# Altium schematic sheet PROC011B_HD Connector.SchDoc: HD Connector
size 431 x 279 mm; Date: Not shown in title block; ApprovedBy: Not shown in title block; CheckedBy: Not shown in title block; Author: Not shown in title block; CompanyName: Not shown in title block; Engineer: Not shown in title block; Organization: Not shown in title block; Address1: Not shown in title block; Address2: Not shown in title block; Address3: Not shown in title block; Address4: Not shown in title block; DocumentNumber: 1; Revision: Use project parameter SCH_Rev; SheetNumber: 11; SheetTotal: 17; PageSetup: Record=PageOptions¦CenterHorizontal=True¦CenterVertical=True¦PrintScale=1.00¦XCorrection=1.00¦YCorrection=1.00¦PrintKind=0¦BorderSize=5000000¦LeftOffset=0¦BottomOffset=0¦Orientation=2¦PaperLength=1000¦PaperWidth=1000¦Scale=100¦PaperSource=15¦PrintQuality=600¦MediaType=1¦DitherType=10¦PrintScaleMode=1¦PaperKind=Letter
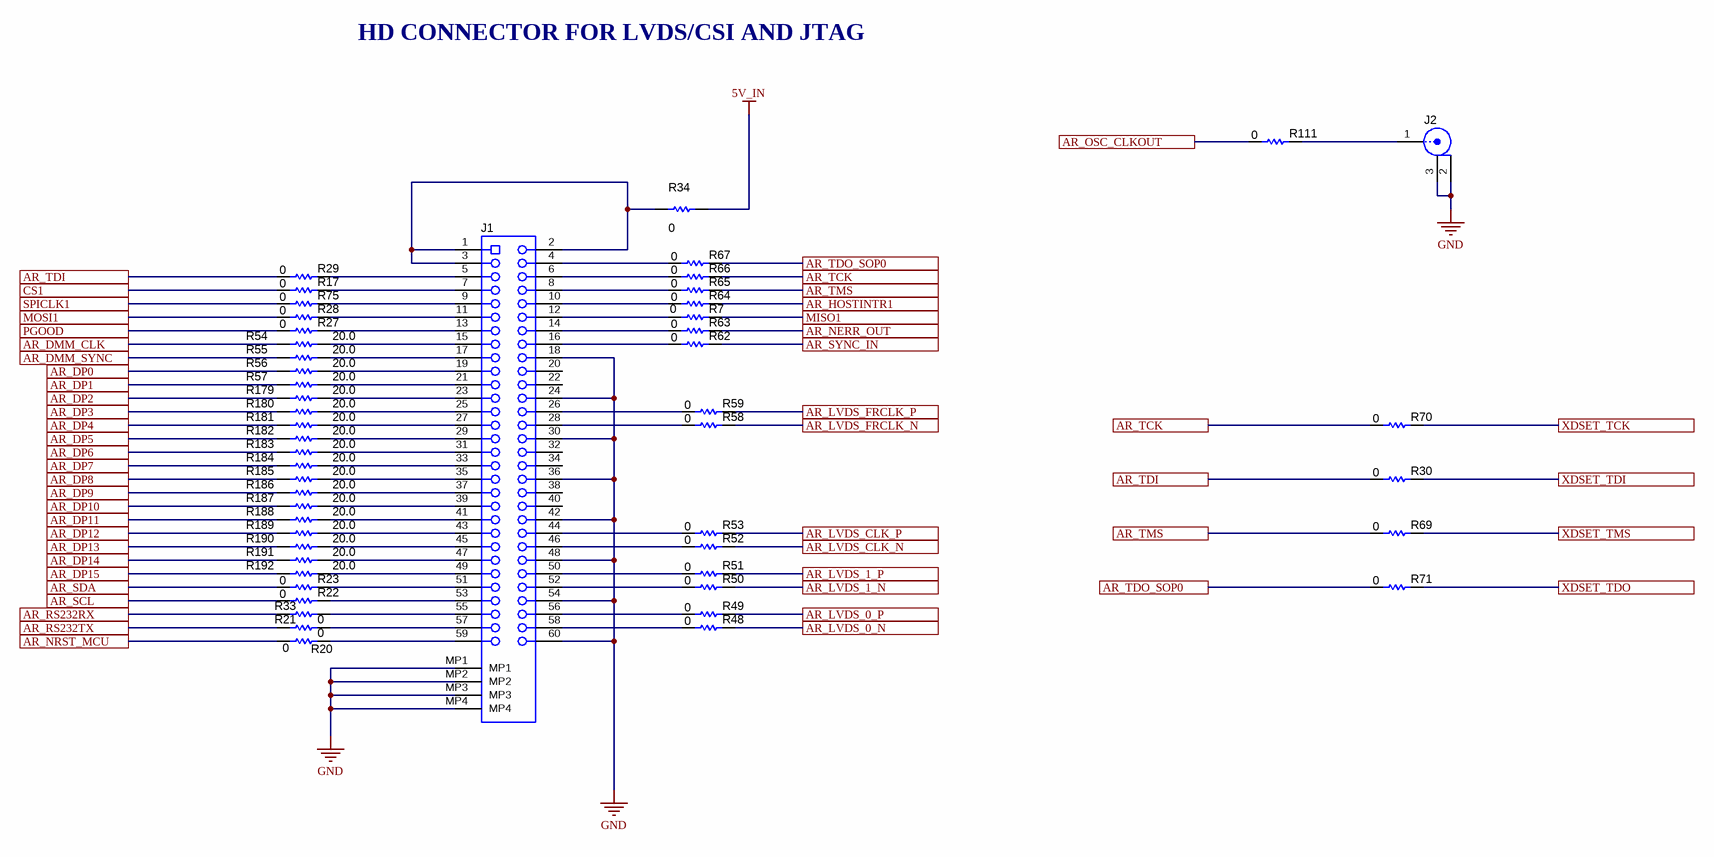
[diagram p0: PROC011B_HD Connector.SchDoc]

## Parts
J1  QSH-030-01-L-D-A  [Samtec_QSH-030-01-X-D-A]  (value not drawn)
J2  128-0711-201  [Johnson_128-0711-201]  (value not drawn)
R7  ValueDisplayed: 0  [0201_Silk]  (hidden comment: CRCW02010000Z0ED)
R17  ValueDisplayed: 0  [0201_Silk]  (hidden comment: CRCW02010000Z0ED)
R20  ValueDisplayed: 0  [0201_Silk]  (hidden comment: CRCW02010000Z0ED)
R21  ValueDisplayed: 0  [0201_Silk]  (hidden comment: CRCW02010000Z0ED)
R22  ValueDisplayed: 0  [0201_Silk]  (hidden comment: CRCW02010000Z0ED)
R23  ValueDisplayed: 0  [0201_Silk]  (hidden comment: CRCW02010000Z0ED)
R27  ValueDisplayed: 0  [0201_Silk]  (hidden comment: CRCW02010000Z0ED)
R28  ValueDisplayed: 0  [0201_Silk]  (hidden comment: CRCW02010000Z0ED)
R29  ValueDisplayed: 0  [0201_Silk]  (hidden comment: CRCW02010000Z0ED)
R30  ValueDisplayed: 0  [0201_Silk]  (hidden comment: CRCW02010000Z0ED)
R33  ValueDisplayed: 0  [0201_Silk]  (hidden comment: CRCW02010000Z0ED)
R34  ValueDisplayed: 0  [2010]  (hidden comment: CRCW20100000Z0EF)
R48  ValueDisplayed: 0  [0201_Silk]  (hidden comment: CRCW02010000Z0ED)
R49  ValueDisplayed: 0  [0201_Silk]  (hidden comment: CRCW02010000Z0ED)
R50  ValueDisplayed: 0  [0201_Silk]  (hidden comment: CRCW02010000Z0ED)
R51  ValueDisplayed: 0  [0201_Silk]  (hidden comment: CRCW02010000Z0ED)
R52  ValueDisplayed: 0  [0201_Silk]  (hidden comment: CRCW02010000Z0ED)
R53  ValueDisplayed: 0  [0201_Silk]  (hidden comment: CRCW02010000Z0ED)
R54  ValueDisplayed: 20.0  [0201_033]  (hidden comment: CRCW020120R0FNED)
R55  ValueDisplayed: 20.0  [0201_033]  (hidden comment: CRCW020120R0FNED)
R56  ValueDisplayed: 20.0  [0201_033]  (hidden comment: CRCW020120R0FNED)
R57  ValueDisplayed: 20.0  [0201_033]  (hidden comment: CRCW020120R0FNED)
R58  ValueDisplayed: 0  [0201_Silk]  (hidden comment: CRCW02010000Z0ED)
R59  ValueDisplayed: 0  [0201_Silk]  (hidden comment: CRCW02010000Z0ED)
R62  ValueDisplayed: 0  [0201_Silk]  (hidden comment: CRCW02010000Z0ED)
R63  ValueDisplayed: 0  [0201_Silk]  (hidden comment: CRCW02010000Z0ED)
R64  ValueDisplayed: 0  [0201_Silk]  (hidden comment: CRCW02010000Z0ED)
R65  ValueDisplayed: 0  [0201_Silk]  (hidden comment: CRCW02010000Z0ED)
R66  ValueDisplayed: 0  [0201_Silk]  (hidden comment: CRCW02010000Z0ED)
R67  ValueDisplayed: 0  [0201_Silk]  (hidden comment: CRCW02010000Z0ED)
R69  ValueDisplayed: 0  [0201_Silk]  (hidden comment: CRCW02010000Z0ED)
R70  ValueDisplayed: 0  [0201_Silk]  (hidden comment: CRCW02010000Z0ED)
R71  ValueDisplayed: 0  [0201_Silk]  (hidden comment: CRCW02010000Z0ED)
R75  ValueDisplayed: 0  [0201_Silk]  (hidden comment: CRCW02010000Z0ED)
R111  ValueDisplayed: 0  [0201_Silk]  (hidden comment: CRCW02010000Z0ED)
R179  ValueDisplayed: 20.0  [0201_033]  (hidden comment: CRCW020120R0FNED)
R180  ValueDisplayed: 20.0  [0201_033]  (hidden comment: CRCW020120R0FNED)
R181  ValueDisplayed: 20.0  [0201_033]  (hidden comment: CRCW020120R0FNED)
R182  ValueDisplayed: 20.0  [0201_033]  (hidden comment: CRCW020120R0FNED)
R183  ValueDisplayed: 20.0  [0201_033]  (hidden comment: CRCW020120R0FNED)
R184  ValueDisplayed: 20.0  [0201_033]  (hidden comment: CRCW020120R0FNED)
R185  ValueDisplayed: 20.0  [0201_033]  (hidden comment: CRCW020120R0FNED)
R186  ValueDisplayed: 20.0  [0201_033]  (hidden comment: CRCW020120R0FNED)
R187  ValueDisplayed: 20.0  [0201_033]  (hidden comment: CRCW020120R0FNED)
R188  ValueDisplayed: 20.0  [0201_033]  (hidden comment: CRCW020120R0FNED)
R189  ValueDisplayed: 20.0  [0201_033]  (hidden comment: CRCW020120R0FNED)
R190  ValueDisplayed: 20.0  [0201_033]  (hidden comment: CRCW020120R0FNED)
R191  ValueDisplayed: 20.0  [0201_033]  (hidden comment: CRCW020120R0FNED)
R192  ValueDisplayed: 20.0  [0201_033]  (hidden comment: CRCW020120R0FNED)

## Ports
AR_DMM_CLK, AR_DMM_SYNC, AR_DP0, AR_DP1, AR_DP2, AR_DP3, AR_DP4, AR_DP5, AR_DP6, AR_DP7, AR_DP8, AR_DP9, AR_DP10, AR_DP11, AR_DP12, AR_DP13, AR_DP14, AR_DP15, AR_HOSTINTR1, AR_LVDS_0_N, AR_LVDS_0_P, AR_LVDS_1_N, AR_LVDS_1_P, AR_LVDS_CLK_N, AR_LVDS_CLK_P, AR_LVDS_FRCLK_N, AR_LVDS_FRCLK_P, AR_NERR_OUT, AR_NRST_MCU, AR_OSC_CLKOUT, AR_RS232RX, AR_RS232TX, AR_SCL, AR_SDA, AR_SYNC_IN, AR_TCK, AR_TDI, AR_TDO_SOP0, AR_TMS, CS1, MISO1, MOSI1, PGOOD, SPICLK1, XDSET_TCK, XDSET_TDI, XDSET_TDO, XDSET_TMS

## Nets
5V_IN: R34.2
GND: J1.18 J1.24 J1.30 J1.36 J1.42 J1.48 J1.54 J1.60 J1.MP1 J1.MP2 J1.MP3 J1.MP4 J2.2 J2.3
AR_DMM_CLK: R54.1 ; port AR_DMM_CLK
AR_DMM_SYNC: R55.1 ; port AR_DMM_SYNC
AR_DP0: R56.1 ; port AR_DP0
AR_DP1: R57.1 ; port AR_DP1
AR_DP2: R179.1 ; port AR_DP2
AR_DP3: R180.1 ; port AR_DP3
AR_DP4: R181.1 ; port AR_DP4
AR_DP5: R182.1 ; port AR_DP5
AR_DP6: R183.1 ; port AR_DP6
AR_DP7: R184.1 ; port AR_DP7
AR_DP8: R185.1 ; port AR_DP8
AR_DP9: R186.1 ; port AR_DP9
AR_DP10: R187.1 ; port AR_DP10
AR_DP11: R188.1 ; port AR_DP11
AR_DP12: R189.1 ; port AR_DP12
AR_DP13: R190.1 ; port AR_DP13
AR_DP14: R191.1 ; port AR_DP14
AR_DP15: R192.1 ; port AR_DP15
AR_HOSTINTR1: R64.2 ; port AR_HOSTINTR1
AR_LVDS_0_N: R48.2 ; port AR_LVDS_0_N
AR_LVDS_0_P: R49.2 ; port AR_LVDS_0_P
AR_LVDS_1_N: R50.2 ; port AR_LVDS_1_N
AR_LVDS_1_P: R51.2 ; port AR_LVDS_1_P
AR_LVDS_CLK_N: R52.2 ; port AR_LVDS_CLK_N
AR_LVDS_CLK_P: R53.2 ; port AR_LVDS_CLK_P
AR_LVDS_FRCLK_N: R58.2 ; port AR_LVDS_FRCLK_N
AR_LVDS_FRCLK_P: R59.2 ; port AR_LVDS_FRCLK_P
AR_NERR_OUT: R63.2 ; port AR_NERR_OUT
AR_NRST_MCU: R20.1 ; port AR_NRST_MCU
AR_OSC_CLKOUT: R111.1 ; port AR_OSC_CLKOUT
AR_RS232RX: R33.1 ; port AR_RS232RX
AR_RS232TX: R21.1 ; port AR_RS232TX
AR_SCL: R22.1 ; port AR_SCL
AR_SDA: R23.1 ; port AR_SDA
AR_SYNC_IN: R62.2 ; port AR_SYNC_IN
AR_TCK: R66.2 R70.1 ; port AR_TCK
AR_TDI: R29.1 R30.1 ; port AR_TDI
AR_TDO_SOP0: R67.2 R71.1 ; port AR_TDO_SOP0
AR_TMS: R65.2 R69.1 ; port AR_TMS
CS1: R17.1 ; port CS1
MISO1: R7.2 ; port MISO1
MOSI1: R28.1 ; port MOSI1
PGOOD: R27.1 ; port PGOOD
SPICLK1: R75.1 ; port SPICLK1
XDSET_TCK: R70.2 ; port XDSET_TCK
XDSET_TDI: R30.2 ; port XDSET_TDI
XDSET_TDO: R71.2 ; port XDSET_TDO
XDSET_TMS: R69.2 ; port XDSET_TMS
NetJ1_1: J1.1 J1.2 J1.3 R34.1
NetJ1_4: J1.4 R67.1
NetJ1_5: J1.5 R29.2
NetJ1_6: J1.6 R66.1
NetJ1_7: J1.7 R17.2
NetJ1_8: J1.8 R65.1
NetJ1_9: J1.9 R75.2
NetJ1_10: J1.10 R64.1
NetJ1_11: J1.11 R28.2
NetJ1_12: J1.12 R7.1
NetJ1_13: J1.13 R27.2
NetJ1_14: J1.14 R63.1
NetJ1_15: J1.15 R54.2
NetJ1_16: J1.16 R62.1
NetJ1_17: J1.17 R55.2
NetJ1_19: J1.19 R56.2
NetJ1_21: J1.21 R57.2
NetJ1_23: J1.23 R179.2
NetJ1_25: J1.25 R180.2
NetJ1_26: J1.26 R59.1
NetJ1_27: J1.27 R181.2
NetJ1_28: J1.28 R58.1
NetJ1_29: J1.29 R182.2
NetJ1_31: J1.31 R183.2
NetJ1_33: J1.33 R184.2
NetJ1_35: J1.35 R185.2
NetJ1_37: J1.37 R186.2
NetJ1_39: J1.39 R187.2
NetJ1_41: J1.41 R188.2
NetJ1_43: J1.43 R189.2
NetJ1_44: J1.44 R53.1
NetJ1_45: J1.45 R190.2
NetJ1_46: J1.46 R52.1
NetJ1_47: J1.47 R191.2
NetJ1_49: J1.49 R192.2
NetJ1_50: J1.50 R51.1
NetJ1_51: J1.51 R23.2
NetJ1_52: J1.52 R50.1
NetJ1_53: J1.53 R22.2
NetJ1_55: J1.55 R33.2
NetJ1_56: J1.56 R49.1
NetJ1_57: J1.57 R21.2
NetJ1_58: J1.58 R48.1
NetJ1_59: J1.59 R20.2
NetJ2_1: J2.1 R111.2

Not connected (* = marked no-connect by the designer): J1 20 22 32 34 38 40

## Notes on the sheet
- HD CONNECTOR FOR LVDS/CSI AND JTAG

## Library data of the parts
J1 = CMP-0075524-1: Receptacle, 0.5 mm, 30x2, Gold, TH; Manufacturer: Samtec; Pitch_mm: 0.5; Gender: Female; Green_REACh: Passed; CT: False; Shrouded: N; RowSpacing_mm: 5.73; Green_Lifecycle: Active; Row_Count: 2
J2 = CMP-0055788-1: UMC Straight Jack Receptacle, 50 Ohm, Gold, SMT; Manufacturer: Cinch Connectivity; CNHeader: FALSE; Gender: Female
R7 R22 R23 = CMP-0027008-3: RES, 0, 5%, 0.05 W, 0201; Manufacturer: Vishay-Dale; Power_W: 50mW; TempCo: ppm/C; Value_Code: 0000; U/M: EA; Value: 0; EIA_Code: E24; SizeX_mm: 0.6; SizeY_mm: 0.3; SizeZ_mm: 0.26; Value2: 0.05W; SizeArea_mm2: 0.18; CompType: Resistor; AEC Qualified: N; AEC Category: Q200
R17 R20 R27-R30 R48-R53 R58 R59 R62-R67 R69-R71 R75 R111 = CMP-0027008-3: RES, 0, 5%, 0.05 W, 0201; Manufacturer: Vishay-Dale; Power_W: 50mW; TempCo: ppm/C; Value_Code: 0000; U/M: EA; Value: 0; EIA_Code: E24; SizeX_mm: 0.6; SizeY_mm: 0.3; SizeZ_mm: 0.26; Value2: 0.05W; SizeArea_mm2: 0.18; AEC Qualified: N; AEC Category: Q200
R21 R33 = CMP-0027008-3: RES, 0, 5%, 0.05 W, 0201; Manufacturer: Vishay-Dale; Power_W: 50mW; TempCo: ppm/C; Value_Code: 0000; U/M: EA; Value: 0; EIA_Code: E24; SizeX_mm: 0.6; SizeY_mm: 0.3; SizeZ_mm: 0.26; Value2: 0.05W; SizeArea_mm2: 0.18; CompType: Resistor; AEC Qualified: N; AEC Category: Q200; INSTALATION: DNP
R34 = CMP-0016044-2: RES, 0, 5%, 0.75 W, AEC-Q200 Grade 0, 2010; Manufacturer: Vishay-Dale; Power_W: 750mW; TempCo: ppm/C; Value_Code: 0000; U/M: EA; Value: 0; EIA_Code: E24; SizeX_mm: 5; SizeY_mm: 2.5; SizeZ_mm: 1.66; Value2: 0.75W; SizeArea_mm2: 12.5; CompType: Resistor; AEC Qualified: Y; AEC Category: Q200; INSTALATION: DNP
R54-R57 R179-R186 R188-R192 = CMP-0078192-1: RES, 20.0, 1%, 0.05 W, 0201; Manufacturer: Vishay-Dale; Value_Code: 20R0; SizeArea_mm2: 0.18; AEC Qualified: N; AEC Category: Q200; Res_ohm: 20; Value: 20.0; SizeZ_mm: 0.33; EIA_Code: E96; TempCo: 200 ppm/C; Power_W: 50mW; VDC_V: 30V; SizeY_mm: 0.3; Value2: 0.05W; U/M: EA; SizeX_mm: 0.6
R187 = CMP-0078192-1: RES, 20.0, 1%, 0.05 W, 0201; Manufacturer: Vishay-Dale; Value_Code: 20R0; SizeArea_mm2: 0.18; AEC Qualified: N; AEC Category: Q200; Res_ohm: 20; Value: 20.0; SizeZ_mm: 0.33; EIA_Code: E96; TempCo: 200 ppm/C; Power_W: 50mW; VDC_V: 30V; SizeY_mm: 0.3; Value2: 0.05W; U/M: EA; CompType: Resistor; SizeX_mm: 0.6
